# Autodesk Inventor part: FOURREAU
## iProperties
Shininess: 64.0
Length Units: 11269
Angle Units: 11279
Time Units: 11290
Mass Units: 11283
Length Display Precision: 3
Angle Display Precision: 2
Compacted: True
Part Number: FOURREAU
Document SubType Name: Modeling
Created: 2004-12
Material: Par défaut
Designer: LEGERET Philippe
Density: 0.0
Volumn: 0.0
Area: 0.0
PropertySet Name: Model Information
Control State: 0
Master: False
Checked Out: False
Author: LEGERET Philippe
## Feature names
1. Révolution1 [Revolution]
2. Perçage1 [Hole]
3. Réseau circulaire1 [Circular Pattern]
4. Extrusion1
